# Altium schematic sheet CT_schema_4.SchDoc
size 211 x 163 mm
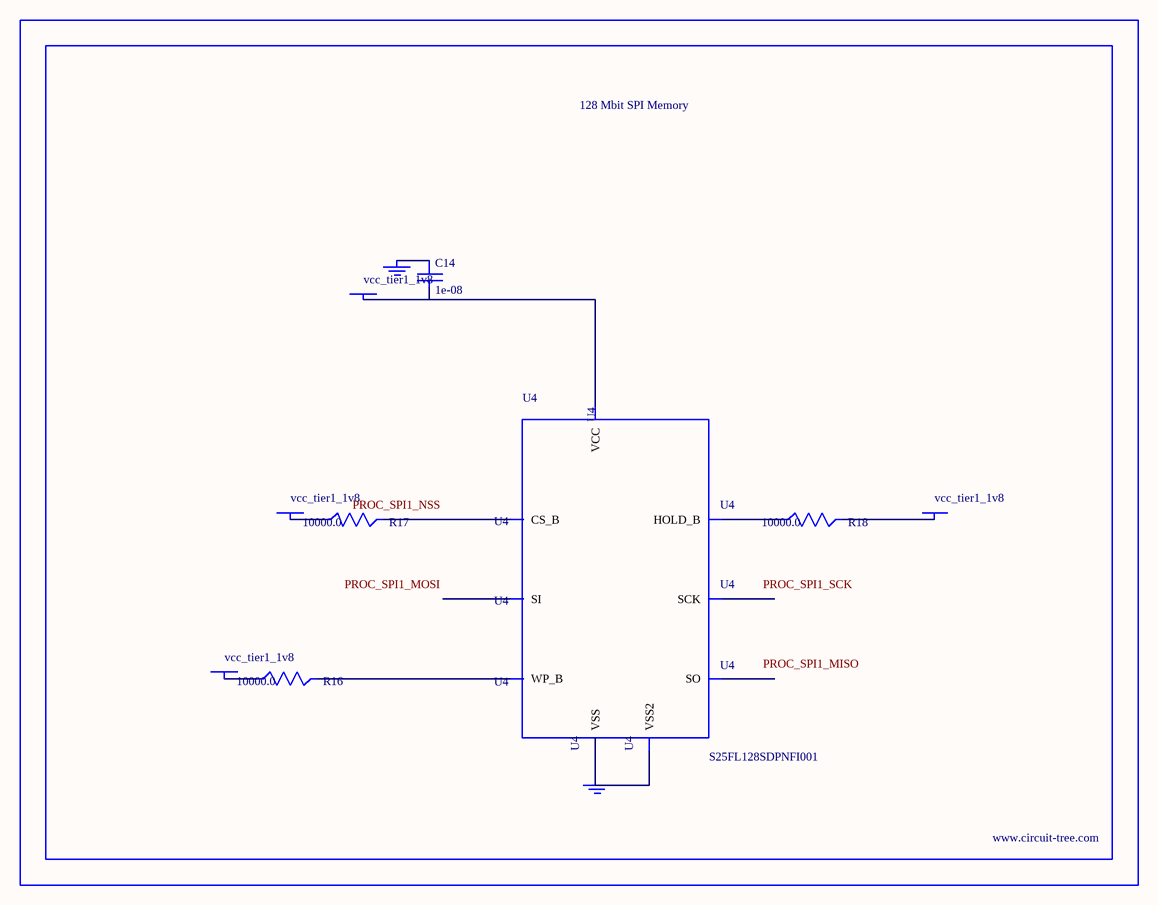
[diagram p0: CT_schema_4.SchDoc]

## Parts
BORDER3  (no value)
C14  1e-08  [C0402]
GND_INSTANCE_3_0  (no value)
GND_INSTANCE_3_1  (no value)
POWER_INSTANCE_3_0  vcc_tier1_1v8
POWER_INSTANCE_3_1  vcc_tier1_1v8
POWER_INSTANCE_3_2  vcc_tier1_1v8
POWER_INSTANCE_3_3  vcc_tier1_1v8
R16  10000.0  [R0603]
R17  10000.0  [R0603]
R18  10000.0  [R0603]
U4  S25FL128SDPNFI001  [WNG008]

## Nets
NetC14_1: C14.1 GND_INSTANCE_3_0.0(GND)
NetC14_2: C14.2 POWER_INSTANCE_3_3.0(PWR) U4.8(VCC)
NetGND_INSTANCE_3_1_0: GND_INSTANCE_3_1.0(GND) U4.4(VSS) U4.PAD(VSS2)
NetPOWER_INSTANCE_3_0_0: POWER_INSTANCE_3_0.0(PWR) R17.1
NetPOWER_INSTANCE_3_1_0: POWER_INSTANCE_3_1.0(PWR) R16.1
NetPOWER_INSTANCE_3_2_0: POWER_INSTANCE_3_2.0(PWR) R18.2
NetR16_2: R16.2 U4.3(WP_B)
NetR17_2: R17.2 U4.1(CS_B)
NetR18_1: R18.1 U4.7(HOLD_B)

Not connected (* = marked no-connect by the designer): U4 2(SO) 5(SI) 6(SCK)

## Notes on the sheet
- Labels drawn without touching a wire or pin: PROC_SPI1_MISO, PROC_SPI1_MOSI, PROC_SPI1_NSS, PROC_SPI1_SCK

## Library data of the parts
BORDER3 = BORDER_PAGE3
C14 = C0402C103K3RAC
GND_INSTANCE_3_0 GND_INSTANCE_3_1 = GND
POWER_INSTANCE_3_0-POWER_INSTANCE_3_3 = PWR
R16-R18 = RC0603JR-0710KL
